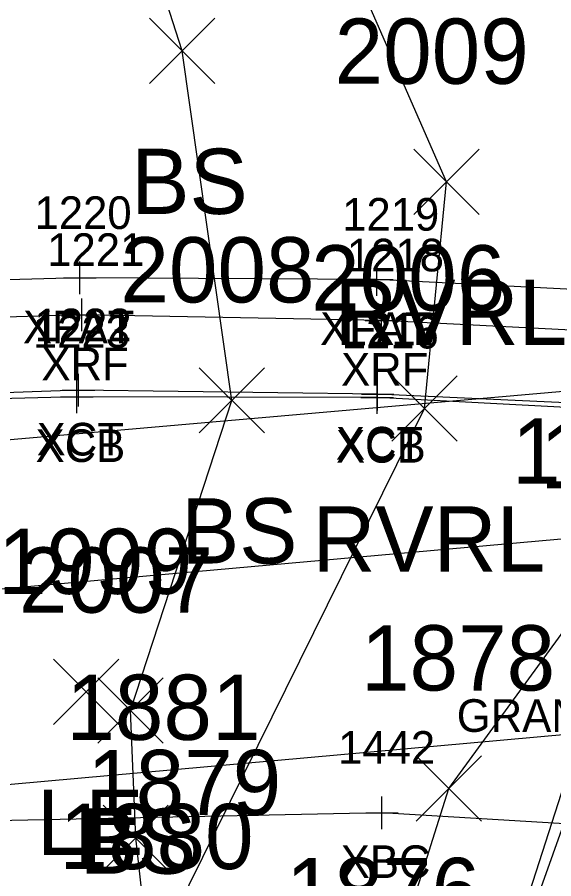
# Model space of a CAD drawing. Extents: x 1638344 to 1639591, y 610835 to 612202.
# Drawn here: x 1638706.21 to 1638722.65, y 611701.7 to 611728.1 of the extents above; entities that cross this region are included whole.
import ezdxf

# ---------------------------------------------------------------- set-up
doc = ezdxf.new("R2010")
doc.units = 0
for name, color, linetype in [('B_A', 7, 'Continuous'), ('B_C', 7, 'Continuous'), ('B_I', 7, 'Continuous'), ('B_TIC', 7, 'Continuous'), ('BB', 7, 'Continuous'), ('BDC', 7, 'Continuous'), ('BELB', 7, 'Continuous'), ('BF', 7, 'Continuous'), ('BR', 7, 'Continuous'), ('BSUBM', 7, 'Continuous'), ('L_A', 7, 'Continuous'), ('L_I', 7, 'Continuous'), ('L_TIC', 7, 'Continuous'), ('LARO', 7, 'Continuous'), ('LAWE', 7, 'Continuous'), ('LELB', 7, 'Continuous')]:
    doc.layers.add(name, color=color, linetype=linetype)

msp = doc.modelspace()

# ---------------------------------------------------------------- linework, layer by layer
at = {"layer": 'B_TIC'}
for p, q in [((1638708.129, 611720.112), (1638708.204, 611720.112)), ((1638717.235, 611720.061), (1638717.31, 611720.061)), ((1638708.193, 611718.979), (1638708.268, 611718.979)), ((1638717.376, 611718.813), (1638717.452, 611718.813)), ((1638708.034, 611716.471), (1638708.11, 611716.471)), ((1638708.086, 611716.671), (1638708.161, 611716.671)), ((1638717.245, 611716.45), (1638717.32, 611716.45)), ((1638717.255, 611716.548), (1638717.331, 611716.548)), ((1638717.388, 611703.723), (1638717.464, 611703.723))]:
    msp.add_line(p, q, dxfattribs=at)
for points in [[(1638708.125, 611719.612), (1638708.125, 611720.612)], [(1638717.231, 611719.561), (1638717.231, 611720.561)], [(1638707.625, 611720.112), (1638708.625, 611720.112)], [(1638716.731, 611720.061), (1638717.731, 611720.061)], [(1638708.189, 611718.479), (1638708.189, 611719.479)], [(1638717.373, 611718.313), (1638717.373, 611719.313)], [(1638707.689, 611718.979), (1638708.689, 611718.979)], [(1638716.873, 611718.813), (1638717.873, 611718.813)], [(1638708.031, 611715.971), (1638708.031, 611716.971)], [(1638708.082, 611716.171), (1638708.082, 611717.171)], [(1638717.252, 611716.048), (1638717.252, 611717.048)], [(1638717.241, 611715.95), (1638717.241, 611716.95)], [(1638707.531, 611716.471), (1638708.531, 611716.471)], [(1638707.582, 611716.671), (1638708.582, 611716.671)], [(1638716.741, 611716.45), (1638717.741, 611716.45)], [(1638716.752, 611716.548), (1638717.752, 611716.548)], [(1638717.385, 611703.223), (1638717.385, 611704.223)], [(1638716.885, 611703.723), (1638717.885, 611703.723)]]:
    msp.add_lwpolyline(points, dxfattribs=at)
at = {"layer": 'BB'}
for points in [[(1638734.87, 611717.669), (1638645.425, 611709.859)], [(1638734.903, 611713.182), (1638645.469, 611705.203)], [(1638735.197, 611707.211), (1638645.609, 611699.159)]]:
    msp.add_lwpolyline(points, dxfattribs=at)
at = {"layer": 'BDC'}
for points in [[(1638737.305, 611718.795), (1638737.221, 611715.93), (1638737.034, 611715.608), (1638736.539, 611715.364), (1638735.749, 611715.325), (1638725.935, 611715.986), (1638717.241, 611716.45), (1638708.031, 611716.471), (1638699.246, 611716.24), (1638689.973, 611715.561), (1638681.851, 611714.706), (1638672.108, 611713.295), (1638663.178, 611711.795), (1638654.252, 611709.944), (1638645.027, 611707.62), (1638643.746, 611707.614), (1638643.485, 611708.194), (1638643.486, 611710.833)], [(1638737.078, 611718.736), (1638737.03, 611716.376), (1638736.823, 611715.856), (1638736.034, 611715.473), (1638725.908, 611716.152), (1638717.252, 611716.548), (1638708.082, 611716.671), (1638699.284, 611716.36), (1638690.06, 611715.643), (1638681.839, 611714.822), (1638672.266, 611713.507), (1638663.196, 611711.921), (1638654.414, 611710.23), (1638644.982, 611707.789), (1638643.919, 611707.854), (1638643.654, 611708.237), (1638643.636, 611710.999)]]:
    msp.add_lwpolyline(points, dxfattribs=at)
at = {"layer": 'BELB'}
msp.add_lwpolyline([(1638736.563, 611702.566), (1638717.385, 611703.723), (1638696.176, 611703.285), (1638674.233, 611701.328), (1638655.658, 611697.489), (1638644.13, 611693.949)], dxfattribs=at)
at = {"layer": 'BF'}
msp.add_lwpolyline([(1638737.078, 611718.736), (1638726.453, 611719.594), (1638717.231, 611720.061), (1638708.125, 611720.112), (1638698.897, 611719.862), (1638689.982, 611719.193), (1638680.734, 611718.15), (1638671.814, 611716.974), (1638662.694, 611715.401), (1638653.774, 611713.573), (1638643.636, 611710.999)], dxfattribs=at)
at = {"layer": 'BR'}
msp.add_lwpolyline([(1638736.42, 611718.625), (1638736.346, 611717.75), (1638726.195, 611718.354), (1638717.373, 611718.813), (1638708.189, 611718.979), (1638699.169, 611718.709), (1638690.094, 611717.999), (1638681.181, 611717.08), (1638672.054, 611715.864), (1638663.017, 611714.299), (1638654.08, 611712.487), (1638644.592, 611710.18), (1638644.314, 611711.068)], dxfattribs=at)
at = {"layer": 'BSUBM'}
msp.add_lwpolyline([(1638734.863, 611687.18), (1638728.186, 611690.971), (1638719.094, 611692.553), (1638725.54, 611710.63), (1638731.852, 611709.284)], dxfattribs=at)
at = {"layer": 'L_TIC'}
for points in [[(1638710.261, 611726.073), (1638712.261, 611728.073)], [(1638712.261, 611726.073), (1638710.261, 611728.073)], [(1638718.359, 611722.061), (1638720.359, 611724.061)], [(1638720.359, 611722.061), (1638718.359, 611724.061)], [(1638711.785, 611715.361), (1638713.785, 611717.361)], [(1638713.785, 611715.361), (1638711.785, 611717.361)], [(1638717.685, 611715.114), (1638719.685, 611717.114)], [(1638719.685, 611715.114), (1638717.685, 611717.114)], [(1638707.317, 611706.428), (1638709.317, 611708.428)], [(1638709.317, 611706.428), (1638707.317, 611708.428)], [(1638708.677, 611705.854), (1638710.677, 611707.854)], [(1638710.677, 611705.854), (1638708.677, 611707.854)], [(1638718.435, 611703.469), (1638720.435, 611705.469)], [(1638720.435, 611703.469), (1638718.435, 611705.469)], [(1638708.836, 611701.955), (1638710.836, 611703.955)], [(1638710.836, 611701.955), (1638708.836, 611703.955)]]:
    msp.add_lwpolyline(points, dxfattribs=at)
at = {"layer": 'LARO'}
msp.add_lwpolyline([(1638720.387, 611665.845), (1638721.028, 611680.57), (1638719.094, 611692.553), (1638724.927, 611710.662), (1638728.568, 611713.859), (1638729.448, 611725.986)], dxfattribs=at)
at = {"layer": 'LAWE'}
msp.add_lwpolyline([(1638671.011, 611601.41), (1638687.934, 611612.159), (1638702.816, 611621.305), (1638722.828, 611637.898), (1638722.694, 611666.366), (1638723.119, 611679.868), (1638719.094, 611692.553), (1638717.187, 611697.341), (1638711.048, 611700.649), (1638718.685, 611716.114), (1638719.359, 611723.061), (1638714.323, 611734.571), (1638714.704, 611747.214), (1638712.56, 611755.84), (1638714.994, 611761.22), (1638711.865, 611767.72), (1638710.522, 611777.786), (1638714.936, 611789.326), (1638716.942, 611806.826), (1638715.698, 611824.36)], dxfattribs=at)
at = {"layer": 'LELB'}
for points in [[(1638721.028, 611680.57), (1638715.476, 611695.81), (1638710.279, 611698.997), (1638709.836, 611702.955), (1638709.677, 611706.854), (1638712.785, 611716.361), (1638711.261, 611727.073), (1638708.812, 611734.706), (1638707.325, 611746.484), (1638710.104, 611757.938)], [(1638717.187, 611697.341), (1638719.435, 611704.469), (1638724.063, 611710.807), (1638726.027, 611716.685), (1638727.673, 611724.518)]]:
    msp.add_lwpolyline(points, dxfattribs=at)

# ---------------------------------------------------------------- texts
at = {"layer": 'B_A'}
for s, p in [('XFAT', (1638706.381, 611718.112)), ('XFAT', (1638715.487, 611718.061)), ('XRF', (1638706.949, 611716.979)), ('XRF', (1638716.132, 611716.813)), ('XCT', (1638706.803, 611714.671)), ('XCB', (1638706.767, 611714.471)), ('XCT', (1638715.972, 611714.548)), ('XCB', (1638715.977, 611714.45)), ('XBC', (1638716.121, 611701.723))]:
    msp.add_text(s, height=1, dxfattribs=at).set_placement(p)
at = {"layer": 'B_C'}
msp.add_text('GRANITE BLOCK', height=1, dxfattribs=at).set_placement((1638719.676, 611706.201))
at = {"layer": 'B_I'}
for s, p in [('1220', (1638706.736, 611721.612)), ('1219', (1638716.165, 611721.561)), ('1221', (1638707.126, 611720.479)), ('1218', (1638716.31, 611720.313)), ('1222', (1638706.736, 611718.171)), ('1223', (1638706.685, 611717.971)), ('1216', (1638716.151, 611717.95)), ('1217', (1638716.189, 611718.048)), ('1442', (1638716.038, 611705.223))]:
    msp.add_text(s, height=1, dxfattribs=at).set_placement(p)
at = {"layer": 'L_A'}
for s, p in [('BS', (1638709.702, 611722.073)), ('RVRL', (1638715.926, 611718.061)), ('BS', (1638711.226, 611711.361)), ('RVRL', (1638715.252, 611711.114)), ('LE', (1638706.805, 611702.428)), ('BS', (1638708.118, 611701.854))]:
    msp.add_text(s, height=2, dxfattribs=at).set_placement(p)
at = {"layer": 'L_I'}
for s, p in [('2009', (1638715.934, 611726.061)), ('2008', (1638709.368, 611719.361)), ('2006', (1638715.213, 611719.114)), ('1883', (1638721.37, 611713.807)), ('1882', (1638722.234, 611713.662)), ('1999', (1638705.616, 611710.428)), ('2007', (1638706.26, 611709.854)), ('1878', (1638716.742, 611707.469)), ('1881', (1638707.71, 611705.955)), ('1879', (1638708.348, 611703.649)), ('1880', (1638707.5, 611701.997)), ('1876', (1638714.439, 611700.341)), ('1876', (1638714.439, 611700.341))]:
    msp.add_text(s, height=2, dxfattribs=at).set_placement(p)

doc.saveas('drawing.dxf')
